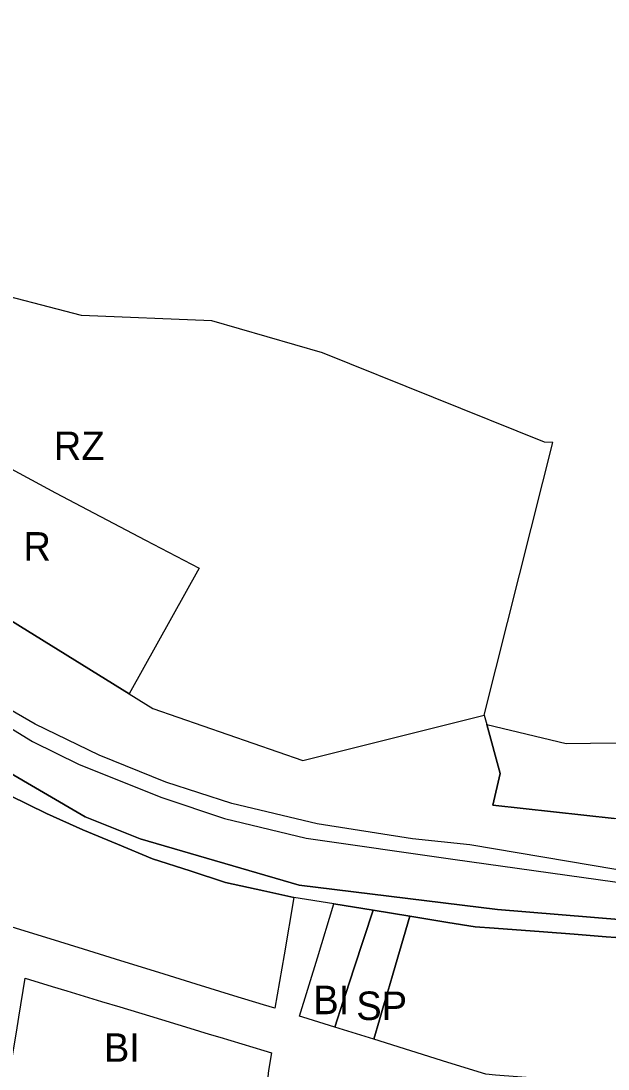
# Model space of a CAD drawing. Extents: x -521621 to -516769, y -1190068 to -1185078.
# Drawn here: x -519733.8 to -519527.8, y -1187252.5 to -1186884.6 of the extents above; entities that cross this region are included whole.
import ezdxf

# ---------------------------------------------------------------- set-up
doc = ezdxf.new("R2010")
doc.units = 0
for name, color, linetype in [('bydleni_s', 7, 'Continuous'), ('rekreace_s', 7, 'Continuous'), ('s_zelen_s', 7, 'Continuous'), ('sm_vyuziti_s', 7, 'Continuous'), ('v_infrastr_s', 7, 'Continuous'), ('voda_s', 7, 'Continuous')]:
    doc.layers.add(name, color=color, linetype=linetype)

msp = doc.modelspace()

# ---------------------------------------------------------------- linework, layer by layer
at = {"layer": 'bydleni_s'}
for p, q in [((-519737.74, -1187156.48), (-519724.84, -1187162.81)), ((-519724.84, -1187162.81), (-519712.08, -1187168.55)), ((-519712.08, -1187168.55), (-519699.89, -1187173.63)), ((-519699.89, -1187173.63), (-519687.61, -1187178.74)), ((-519687.61, -1187178.74), (-519674.45, -1187183.01)), ((-519674.45, -1187183.01), (-519661.97, -1187187.05)), ((-519661.97, -1187187.05), (-519648.59, -1187189.99)), ((-519725.01, -1187206.42), (-519738.4, -1187202.29)), ((-519711.87, -1187210.48), (-519725.01, -1187206.42)), ((-519698.75, -1187214.53), (-519711.87, -1187210.48)), ((-519685.41, -1187218.65), (-519698.75, -1187214.53)), ((-519672.31, -1187222.7), (-519685.41, -1187218.65)), ((-519659.05, -1187226.79), (-519672.31, -1187222.7)), ((-519717.7, -1187225.1), (-519705.52, -1187228.79)), ((-519705.52, -1187228.79), (-519699.07, -1187230.75)), ((-519699.07, -1187230.75), (-519688.73, -1187233.89)), ((-519688.73, -1187233.89), (-519674.48, -1187238.21))]:
    msp.add_line(p, q, dxfattribs=at)
for points in [[(-519648.59, -1187189.99), (-519637.97, -1187192.32), (-519641.45, -1187212.48)], [(-519629.77, -1187213.54), (-519623.96, -1187194.59), (-519610.17, -1187196.82), (-519616.82, -1187217.04)], [(-519603.17, -1187218.86), (-519597.31, -1187198.91), (-519583.92, -1187201.08)], [(-519583.92, -1187201.08), (-519574.39, -1187202.62)], [(-519574.39, -1187202.62), (-519567.68, -1187203.12)], [(-519567.68, -1187203.12), (-519550.44, -1187204.42)], [(-519550.44, -1187204.42), (-519539.69, -1187205.23)], [(-519539.69, -1187205.23), (-519528.42, -1187206.07)], [(-519528.42, -1187206.07), (-519518.19, -1187206.84)], [(-519641.45, -1187212.48), (-519644.68, -1187231.23), (-519648.69, -1187229.99), (-519659.05, -1187226.79)], [(-519616.82, -1187217.04), (-519619.77, -1187226), (-519620.68, -1187228.77), (-519623.65, -1187237.81), (-519634.88, -1187234.3), (-519636.03, -1187233.94), (-519629.77, -1187213.54)], [(-519596.96, -1187246.17), (-519609.99, -1187242.09), (-519607.99, -1187235.29), (-519606.53, -1187230.3), (-519604.49, -1187223.37), (-519603.17, -1187218.86)], [(-519737.73, -1187260.72), (-519737.35, -1187254.2), (-519737.12, -1187250.04), (-519735.38, -1187239.55), (-519734.51, -1187234.3), (-519732.25, -1187220.68), (-519722.78, -1187223.56), (-519717.7, -1187225.1)], [(-519674.48, -1187238.21), (-519667.79, -1187240.25), (-519663.98, -1187241.4), (-519648.55, -1187246.09), (-519645.83, -1187246.91), (-519646.91, -1187253.08), (-519647.41, -1187257.68), (-519649.63, -1187272.01), (-519654.84, -1187271.31), (-519664.38, -1187268.46), (-519667.11, -1187267.65), (-519678.78, -1187265.99), (-519680.67, -1187265.72), (-519692.44, -1187264.04), (-519692.17, -1187261.06), (-519693.98, -1187261.03), (-519700.87, -1187260.9), (-519708.93, -1187260.55)], [(-519584.02, -1187250.22), (-519596.96, -1187246.17)], [(-519567.27, -1187254.65), (-519570.68, -1187254.39), (-519584.02, -1187250.22)]]:
    msp.add_lwpolyline(points, dxfattribs=at)
at = {"layer": 'rekreace_s'}
for points in [[(-519547.18, -1187032.53), (-519550.02, -1187032.47), (-519627.99, -1187001.07), (-519666.78, -1186989.91), (-519712.58, -1186987.97), (-519749.55, -1186978.37), (-519765.51, -1186975.38), (-519769.39, -1186982.4)], [(-519695.81, -1187120.87), (-519687.54, -1187126), (-519634.87, -1187144.17), (-519571.17, -1187128.34), (-519550.67, -1187046.48), (-519547.18, -1187032.53)], [(-519759.25, -1187080.06), (-519740.02, -1187040.35), (-519721.62, -1187050.23), (-519690.13, -1187066.85), (-519671.19, -1187076.71), (-519695.81, -1187120.87)]]:
    msp.add_lwpolyline(points, dxfattribs=at)
msp.add_lwpolyline([(-519721.62, -1187050.23), (-519690.13, -1187066.85), (-519671.19, -1187076.71), (-519695.81, -1187120.87), (-519739.82, -1187093.57), (-519759.25, -1187080.06), (-519740.02, -1187040.35)], close=True, dxfattribs=at)
at = {"layer": 's_zelen_s'}
for points in [[(-519976.25, -1186969.59), (-519973.89, -1186964.34), (-519945.18, -1186982.09), (-519941.17, -1186985.33), (-519876.04, -1187044.95), (-519872.07, -1187048.29), (-519870.88, -1187049.41), (-519831.64, -1187086.03), (-519782.87, -1187121.37), (-519783.03, -1187122.14), (-519711.27, -1187163.96), (-519691.98, -1187171.68), (-519636.11, -1187188.04), (-519566.51, -1187196.52), (-519488.58, -1187203.01), (-519374.38, -1187202.7), (-519363.08, -1187202.74), (-519276.38, -1187203.01), (-519187.84, -1187203.66), (-519142.54, -1187204.74), (-519110.53, -1187206.31), (-519088.84, -1187207.37)], [(-519518.19, -1187206.84), (-519528.42, -1187206.07), (-519539.69, -1187205.23), (-519550.44, -1187204.42), (-519567.68, -1187203.12), (-519574.39, -1187202.62), (-519583.92, -1187201.08), (-519597.31, -1187198.91), (-519610.17, -1187196.82), (-519623.96, -1187194.59), (-519637.97, -1187192.32), (-519648.59, -1187189.99), (-519661.97, -1187187.05), (-519674.45, -1187183.01), (-519687.61, -1187178.74), (-519699.89, -1187173.63), (-519712.08, -1187168.55), (-519724.84, -1187162.81), (-519737.74, -1187156.48)]]:
    msp.add_lwpolyline(points, dxfattribs=at)
at = {"layer": 'sm_vyuziti_s'}
for points in [[(-519619.77, -1187226), (-519616.82, -1187217.04), (-519610.17, -1187196.82), (-519597.31, -1187198.91), (-519603.17, -1187218.86), (-519604.49, -1187223.37), (-519606.53, -1187230.3)], [(-519606.53, -1187230.3), (-519607.99, -1187235.29), (-519609.99, -1187242.09), (-519623.65, -1187237.81), (-519620.68, -1187228.77), (-519619.77, -1187226)]]:
    msp.add_lwpolyline(points, dxfattribs=at)
at = {"layer": 'v_infrastr_s'}
for points in [[(-519739.82, -1187093.57), (-519687.54, -1187126)], [(-519728.74, -1187131.52), (-519750.27, -1187119.06)], [(-519687.54, -1187126), (-519634.87, -1187144.17)], [(-519634.87, -1187144.17), (-519571.17, -1187128.34)], [(-519571.17, -1187128.34), (-519570.28, -1187131.58)], [(-519706.31, -1187142.38), (-519728.74, -1187131.52)], [(-519570.28, -1187131.58), (-519565.59, -1187148.78)], [(-519682.99, -1187151.85), (-519706.31, -1187142.38)], [(-519565.59, -1187148.78), (-519568.17, -1187159.87)], [(-519659.77, -1187159.32), (-519682.99, -1187151.85)], [(-519629.87, -1187166.5), (-519659.77, -1187159.32)], [(-519568.17, -1187159.87), (-519525.62, -1187164.56)], [(-519596.38, -1187171.68), (-519629.87, -1187166.5)], [(-519576.25, -1187173.88), (-519596.38, -1187171.68)], [(-519525.02, -1187182.45), (-519576.25, -1187173.88)], [(-519636.03, -1187233.94), (-519629.77, -1187213.54), (-519623.96, -1187194.59), (-519637.97, -1187192.32), (-519641.45, -1187212.48), (-519644.68, -1187231.23)], [(-519644.68, -1187231.23), (-519648.69, -1187229.99), (-519659.05, -1187226.79), (-519672.31, -1187222.7), (-519685.41, -1187218.65), (-519698.75, -1187214.53), (-519711.87, -1187210.48), (-519725.01, -1187206.42), (-519738.4, -1187202.29)], [(-519737.35, -1187254.2), (-519737.12, -1187250.04), (-519735.38, -1187239.55), (-519734.51, -1187234.3), (-519732.25, -1187220.68), (-519722.78, -1187223.56), (-519717.7, -1187225.1), (-519705.52, -1187228.79), (-519699.07, -1187230.75), (-519688.73, -1187233.89), (-519674.48, -1187238.21), (-519667.79, -1187240.25), (-519663.98, -1187241.4), (-519648.55, -1187246.09), (-519645.83, -1187246.91), (-519646.91, -1187253.08)], [(-519506.63, -1187270.05), (-519509.72, -1187269.62), (-519519.87, -1187268.2), (-519519.83, -1187264.35), (-519530.22, -1187263.31), (-519530.1, -1187261.78), (-519540.33, -1187260.82), (-519540.49, -1187262.59), (-519545.51, -1187262.1), (-519545.47, -1187259.34), (-519550.52, -1187259.06), (-519550.28, -1187255.93), (-519567.27, -1187254.65), (-519570.68, -1187254.39), (-519584.02, -1187250.22), (-519596.96, -1187246.17), (-519609.99, -1187242.09), (-519623.65, -1187237.81), (-519634.88, -1187234.3), (-519636.03, -1187233.94)]]:
    msp.add_lwpolyline(points, dxfattribs=at)
msp.add_lwpolyline([(-519471.58, -1187166.09), (-519520.78, -1187164.7), (-519525.62, -1187164.56), (-519568.17, -1187159.87), (-519565.59, -1187148.78), (-519570.28, -1187131.58), (-519542.51, -1187138.24), (-519533.88, -1187138.14), (-519511.41, -1187137.88), (-519479.95, -1187136.97), (-519439.45, -1187145.43), (-519434.32, -1187146.5), (-519379.97, -1187139), (-519374.79, -1187138.62), (-519373.47, -1187147.63), (-519370.95, -1187164.84), (-519370.6, -1187167.23), (-519393.07, -1187167.04), (-519431.2, -1187166.58)], close=True, dxfattribs=at)
at = {"layer": 'voda_s'}
for points in [[(-520317.35, -1186794.57), (-520183.23, -1186854.16), (-520082.33, -1186900.21), (-519990.94, -1186942.77), (-519990.94, -1186942.77), (-519972.47, -1186951.37), (-519950.32, -1186964.73), (-519911.12, -1186993.2), (-519867.23, -1187034.17), (-519863.47, -1187037.69), (-519821.12, -1187077.22), (-519809.35, -1187086.01), (-519777.18, -1187107.81), (-519749.23, -1187125.56), (-519729.72, -1187137.52), (-519713.37, -1187145.6), (-519684.37, -1187157.2), (-519662.4, -1187164.59), (-519633.74, -1187171.44), (-519582.24, -1187178.82), (-519519.49, -1187187.61)], [(-519488.58, -1187203.01), (-519566.51, -1187196.52), (-519636.11, -1187188.04), (-519691.98, -1187171.68), (-519711.27, -1187163.96), (-519783.03, -1187122.14), (-519782.87, -1187121.37), (-519831.64, -1187086.03), (-519870.88, -1187049.41), (-519872.07, -1187048.29), (-519876.04, -1187044.95), (-519941.17, -1186985.33), (-519945.18, -1186982.09), (-519973.89, -1186964.34), (-519976.25, -1186969.59)]]:
    msp.add_lwpolyline(points, dxfattribs=at)

# ---------------------------------------------------------------- texts
at = {"layer": 'bydleni_s'}
for p in [(-519631.19, -1187233.29), (-519704.68, -1187250.01)]:
    msp.add_text('BI', height=10, dxfattribs=at).set_placement(p)
at = {"layer": 'rekreace_s'}
for s, p in [('RZ', (-519722.26, -1187038.73)), ('R', (-519732.92, -1187074.04))]:
    msp.add_text(s, height=10, dxfattribs=at).set_placement(p)
at = {"layer": 'sm_vyuziti_s'}
msp.add_text('SP', height=10, dxfattribs=at).set_placement((-519616.11, -1187235.33))

doc.saveas('drawing.dxf')
